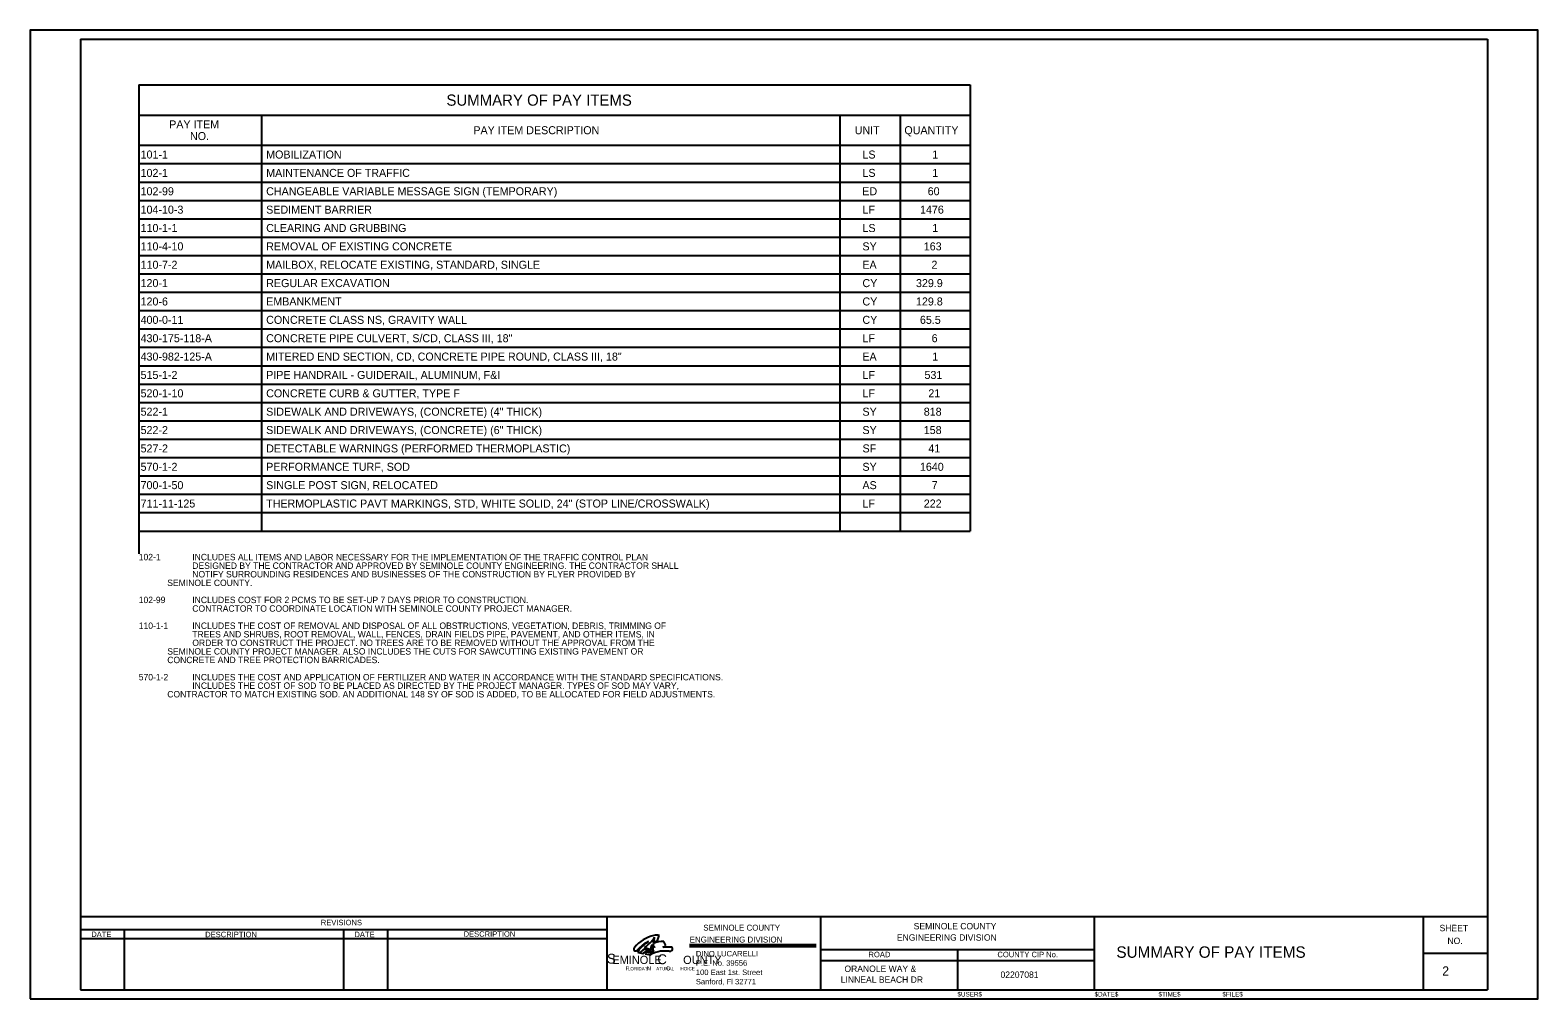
# Model space of a CAD drawing. Extents: x -792.8 to -776.3, y -2147.8 to -2137.2.
import ezdxf

# ---------------------------------------------------------------- set-up
doc = ezdxf.new("R2010")
doc.units = 0
for name, color, linetype in [('AdhocPoint_dp', 7, 'Continuous'), ('Default', 7, 'Continuous'), ('Logo_dp', 7, 'Continuous'), ('NonPlottingEle_dp', 7, 'Continuous'), ('PlotBorder_dp', 7, 'Continuous'), ('ScratchEle_dp', 7, 'Continuous'), ('SheetBorder_dp', 7, 'Continuous'), ('SheetLines_dp', 7, 'Continuous'), ('SumBoxBorder_dp', 7, 'Continuous'), ('SumBoxLines_dp', 7, 'Continuous'), ('SumBoxLinesMin_dp', 7, 'Continuous'), ('TextLabel', 7, 'Continuous'), ('TextMinor', 7, 'Continuous'), ('TextMisc', 7, 'Continuous'), ('TextShtNo', 7, 'Continuous')]:
    doc.layers.add(name, color=color, linetype=linetype)

msp = doc.modelspace()

# ---------------------------------------------------------------- linework, layer by layer
at = {"layer": 'AdhocPoint_dp'}
msp.add_line((-792.826, -2147.841), (-792.826, -2147.841), dxfattribs=at)
at = {"layer": 'Logo_dp'}
for p, q in [((-786.082, -2147.321), (-786.082, -2147.306)), ((-786.065, -2147.31), (-786.051, -2147.301)), ((-785.965, -2147.213), (-785.94, -2147.149)), ((-785.812, -2147.276), (-785.901, -2147.274)), ((-785.868, -2147.258), (-785.892, -2147.212)), ((-786.153, -2147.339), (-786.119, -2147.346)), ((-786.119, -2147.346), (-786.082, -2147.321)), ((-786.096, -2147.35), (-786.036, -2147.359)), ((-786.001, -2147.313), (-786.014, -2147.334))]:
    msp.add_line(p, q, dxfattribs=at)
for points in [[(-786.147, -2147.288), (-786.147, -2147.288)], [(-785.999, -2147.148), (-785.999, -2147.148)]]:
    msp.add_lwpolyline(points, dxfattribs=at)
for centre, radius, start, end in [((-785.971, -2147.269), 0.124, 75.3253, 102.9903), ((-786.189, -2147.297), 0.0305, 139.6059, 196.4516), ((-786.204, -2147.302), 0.015, 196.4516, 259.2243), ((-785.91, -2147.535), 0.397, 102.9903, 139.6059), ((-786.201, -2147.289), 0.0281, 259.2243, 316.3038), ((-785.905, -2147.544), 0.363, 114.9659, 139.5324), ((-786.063, -2147.368), 0.116, 136.5671, 163.5792), ((-785.974, -2147.497), 0.238, 117.2749, 138.5612), ((-785.974, -2147.497), 0.238, 117.2749, 138.5612), ((-785.805, -2147.612), 0.471, 122.4911, 136.5671), ((-786.397, -2146.85), 0.52, 304.6341, 315.4846), ((-786.128, -2147.373), 0.0982, 63.4009, 74.6531), ((-786.097, -2147.309), 0.0152, 9.3089, 39.4038), ((-786.092, -2147.327), 0.0288, 52.8844, 76.2699), ((-786.235, -2147.627), 0.374, 60.5981, 66.1485), ((-786.045, -2147.266), 0.0482, 231.8585, 245.4301), ((-785.687, -2147.855), 0.656, 120.5054, 124.3665), ((-785.868, -2147.333), 0.173, 149.8559, 166.6084), ((-785.883, -2147.578), 0.324, 115.0847, 118.1751), ((-786.152, -2147.091), 0.176, 315.4846, 334.5843), ((-785.917, -2147.273), 0.104, 164.7271, 186.2913), ((-785.982, -2147.285), 0.0385, 187.6078, 223.6575), ((-785.687, -2147.855), 0.656, 117.0216, 119.5789), ((-785.696, -2147.3), 0.315, 177.2074, 179.7242), ((-785.968, -2147.3), 0.0427, 177.7479, 195.3391), ((-785.696, -2147.3), 0.315, 168.5397, 176.4368), ((-785.883, -2147.578), 0.324, 108.2919, 113.1245), ((-785.897, -2147.455), 0.243, 88.8097, 116.3253), ((-786.217, -2147.161), 0.224, 343.2724, 358.4983), ((-785.925, -2147.392), 0.184, 102.6743, 114.927), ((-785.936, -2147.158), 0.122, 286.9862, 304.2368), ((-785.811, -2147.292), 0.0161, 0.9885, 92.5741), ((-785.822, -2147.294), 0.0268, 319.3898, 5.6197), ((-786.252, -2147.801), 0.472, 77.906, 80.5112), ((-785.823, -2147.569), 0.35, 136.6419, 141.2542), ((-786.031, -2147.132), 0.202, 256.604, 274.8219), ((-786.029, -2147.26), 0.0603, 242.5498, 297.6527), ((-785.854, -2147.706), 0.392, 100.5294, 117.6775), ((-785.878, -2147.844), 0.526, 84.8254, 95.1746), ((-785.826, -2147.282), 0.0383, 262.9671, 309.9257)]:
    msp.add_arc(centre, radius, start, end, dxfattribs=at)
at = {"layer": 'NonPlottingEle_dp'}
msp.add_line((-791.637, -2142.722), (-791.637, -2142.972), dxfattribs=at)
at = {"layer": 'PlotBorder_dp'}
msp.add_lwpolyline([(-792.826, -2147.841), (-776.326, -2147.841), (-776.326, -2137.241), (-792.826, -2137.241)], close=True, dxfattribs=at)
at = {"layer": 'SheetBorder_dp'}
for p, q in [((-792.276, -2137.341), (-792.276, -2147.741)), ((-792.276, -2137.341), (-776.876, -2137.341)), ((-776.876, -2137.341), (-776.876, -2147.741)), ((-792.276, -2146.941), (-776.876, -2146.941)), ((-792.276, -2147.741), (-776.876, -2147.741))]:
    msp.add_line(p, q, dxfattribs=at)
at = {"layer": 'SheetLines_dp'}
for p, q in [((-786.516, -2146.941), (-786.516, -2147.741)), ((-784.176, -2146.941), (-784.176, -2147.741)), ((-781.176, -2147.741), (-781.176, -2146.941)), ((-777.576, -2147.741), (-777.576, -2146.941)), ((-792.276, -2147.081), (-786.516, -2147.081)), ((-791.796, -2147.081), (-791.796, -2147.741)), ((-789.396, -2147.081), (-789.396, -2147.741)), ((-788.916, -2147.081), (-788.916, -2147.741)), ((-792.276, -2147.181), (-786.516, -2147.181)), ((-784.176, -2147.301), (-781.176, -2147.301)), ((-782.676, -2147.301), (-782.676, -2147.741)), ((-784.176, -2147.421), (-781.176, -2147.421)), ((-777.576, -2147.341), (-776.876, -2147.341))]:
    msp.add_line(p, q, dxfattribs=at)
at = {"layer": 'SumBoxBorder_dp'}
for p, q in [((-791.637, -2137.841), (-782.54, -2137.841)), ((-791.637, -2137.841), (-791.637, -2142.722)), ((-782.54, -2137.841), (-782.54, -2142.722)), ((-791.637, -2138.171), (-782.54, -2138.171)), ((-791.637, -2142.722), (-782.54, -2142.722))]:
    msp.add_line(p, q, dxfattribs=at)
at = {"layer": 'SumBoxLines_dp'}
for p, q in [((-790.295, -2138.171), (-790.295, -2142.722)), ((-790.295, -2138.171), (-790.295, -2142.722)), ((-783.965, -2138.171), (-783.965, -2142.722)), ((-783.965, -2138.171), (-783.965, -2142.722)), ((-783.305, -2138.171), (-783.305, -2142.722)), ((-783.305, -2138.171), (-783.305, -2142.722)), ((-791.637, -2138.501), (-782.54, -2138.501))]:
    msp.add_line(p, q, dxfattribs=at)
at = {"layer": 'SumBoxLinesMin_dp'}
for p, q in [((-791.637, -2138.501), (-782.54, -2138.501)), ((-791.637, -2138.702), (-782.54, -2138.702)), ((-791.637, -2138.702), (-782.54, -2138.702)), ((-791.637, -2138.903), (-782.54, -2138.903)), ((-791.637, -2138.903), (-782.54, -2138.903)), ((-791.637, -2139.104), (-782.54, -2139.104)), ((-791.637, -2139.104), (-782.54, -2139.104)), ((-791.637, -2139.305), (-782.54, -2139.305)), ((-791.637, -2139.305), (-782.54, -2139.305)), ((-791.637, -2139.506), (-782.54, -2139.506)), ((-791.637, -2139.506), (-782.54, -2139.506)), ((-791.637, -2139.707), (-782.54, -2139.707)), ((-791.637, -2139.707), (-782.54, -2139.707)), ((-791.637, -2139.908), (-782.54, -2139.908)), ((-791.637, -2139.908), (-782.54, -2139.908)), ((-791.637, -2140.109), (-782.54, -2140.109)), ((-791.637, -2140.109), (-782.54, -2140.109)), ((-791.637, -2140.31), (-782.54, -2140.31)), ((-791.637, -2140.31), (-782.54, -2140.31)), ((-791.637, -2140.511), (-782.54, -2140.511)), ((-791.637, -2140.511), (-782.54, -2140.511)), ((-791.637, -2140.712), (-782.54, -2140.712)), ((-791.637, -2140.712), (-782.54, -2140.712)), ((-791.637, -2140.913), (-782.54, -2140.913)), ((-791.637, -2140.913), (-782.54, -2140.913)), ((-791.637, -2141.114), (-782.54, -2141.114)), ((-791.637, -2141.114), (-782.54, -2141.114)), ((-791.637, -2141.315), (-782.54, -2141.315)), ((-791.637, -2141.315), (-782.54, -2141.315)), ((-791.637, -2141.516), (-782.54, -2141.516)), ((-791.637, -2141.516), (-782.54, -2141.516)), ((-791.637, -2141.717), (-782.54, -2141.717)), ((-791.637, -2141.717), (-782.54, -2141.717)), ((-791.637, -2141.918), (-782.54, -2141.918)), ((-791.637, -2141.918), (-782.54, -2141.918)), ((-791.637, -2142.119), (-782.54, -2142.119)), ((-791.637, -2142.119), (-782.54, -2142.119)), ((-791.637, -2142.32), (-782.54, -2142.32)), ((-791.637, -2142.32), (-782.54, -2142.32)), ((-791.637, -2142.521), (-782.54, -2142.521)), ((-791.637, -2142.521), (-782.54, -2142.521))]:
    msp.add_line(p, q, dxfattribs=at)
at = {"layer": 'TextMisc'}
for p, q in [((-785.611, -2147.269), (-784.225, -2147.269)), ((-785.609, -2147.247), (-784.223, -2147.247))]:
    msp.add_line(p, q, dxfattribs=at)

# ---------------------------------------------------------------- texts
at = {"layer": 'Default'}
for s, p in [('102-1', (-791.637, -2143.042)), (' INCLUDES ALL ITEMS AND LABOR NECESSARY FOR THE IMPLEMENTATION OF THE TRAFFIC CONTROL PLAN', (-791.077, -2143.042)), (' DESIGNED BY THE CONTRACTOR AND APPROVED BY SEMINOLE COUNTY ENGINEERING. THE CONTRACTOR SHALL', (-791.077, -2143.136)), (' NOTIFY SURROUNDING RESIDENCES AND BUSINESSES OF THE CONSTRUCTION BY FLYER PROVIDED BY ', (-791.077, -2143.23)), ('            SEMINOLE COUNTY.', (-791.637, -2143.324)), ('102-99', (-791.637, -2143.511)), (' INCLUDES COST FOR 2 PCMS TO BE SET-UP 7 DAYS PRIOR TO CONSTRUCTION.  ', (-791.077, -2143.511)), (' CONTRACTOR TO COORDINATE LOCATION WITH SEMINOLE COUNTY PROJECT MANAGER.', (-791.077, -2143.605)), ('110-1-1', (-791.637, -2143.793)), (' TREES AND SHRUBS, ROOT REMOVAL, WALL, FENCES, DRAIN FIELDS PIPE, PAVEMENT, AND OTHER ITEMS, IN ', (-791.077, -2143.887)), (' INCLUDES THE COST OF REMOVAL AND DISPOSAL OF ALL OBSTRUCTIONS, VEGETATION, DEBRIS, TRIMMING OF ', (-791.077, -2143.793)), ('            SEMINOLE COUNTY PROJECT MANAGER. ALSO INCLUDES THE CUTS FOR SAWCUTTING EXISTING PAVEMENT OR ', (-791.637, -2144.074)), (' ORDER TO CONSTRUCT THE PROJECT. NO TREES ARE TO BE REMOVED WITHOUT THE APPROVAL FROM THE ', (-791.077, -2143.98)), ('            CONCRETE AND TREE PROTECTION BARRICADES.', (-791.637, -2144.168)), ('570-1-2 ', (-791.637, -2144.356)), (' INCLUDES THE COST AND APPLICATION OF FERTILIZER AND WATER IN ACCORDANCE WITH THE STANDARD SPECIFICATIONS. ', (-791.077, -2144.356)), ('            CONTRACTOR TO MATCH EXISTING SOD. AN ADDITIONAL 148 SY OF SOD IS ADDED, TO BE ALLOCATED FOR FIELD ADJUSTMENTS.', (-791.637, -2144.543)), (' INCLUDES THE COST OF SOD TO BE PLACED AS DIRECTED BY THE PROJECT MANAGER. TYPES OF SOD MAY VARY,', (-791.077, -2144.449))]:
    msp.add_text(s, height=0.07, dxfattribs=at).set_placement(p)
at = {"layer": 'Logo_dp'}
for s, height, p in [('S', 0.108, (-786.513, -2147.456)), ('EMINOLE       OUNTY', 0.09, (-786.455, -2147.46)), ('C', 0.108, (-785.961, -2147.462)), ('F', 0.045, (-786.309, -2147.531)), ("LORIDA'S      ATURAL     HOICE", 0.036, (-786.285, -2147.529)), ('N', 0.045, (-786.075, -2147.531)), ('C', 0.045, (-785.866, -2147.531))]:
    msp.add_text(s, height=height, dxfattribs=at).set_placement(p)
at = {"layer": 'ScratchEle_dp'}
for s, p in [('Angle:  90.0153', (-792.276, -2146.943)), ('Align: CH269', (-792.276, -2146.947)), ('Sheet: 1', (-792.276, -2146.939))]:
    msp.add_text(s, height=0.00295, dxfattribs=at).set_placement(p)
at = {"layer": 'TextLabel'}
for s, height, p in [('SUMMARY OF PAY ITEMS', 0.1225, (-788.27, -2138.068)), ('PAY ITEM', 0.0875, (-791.304, -2138.316)), ('NO.', 0.0875, (-791.076, -2138.444)), ('PAY ITEM DESCRIPTION', 0.0875, (-787.975, -2138.38)), ('UNIT', 0.0875, (-783.802, -2138.38)), ('QUANTITY', 0.0875, (-783.258, -2138.38)), ('101-1', 0.0875, (-791.617, -2138.646)), (' MOBILIZATION', 0.0875, (-790.275, -2138.646)), ('LS', 0.0875, (-783.717, -2138.646)), ('1', 0.0875, (-782.953, -2138.646)), ('102-1', 0.0875, (-791.617, -2138.847)), (' MAINTENANCE OF TRAFFIC', 0.0875, (-790.275, -2138.847)), ('LS', 0.0875, (-783.717, -2138.847)), ('1', 0.0875, (-782.953, -2138.847)), ('102-99', 0.0875, (-791.617, -2139.048)), (' CHANGEABLE VARIABLE MESSAGE SIGN (TEMPORARY)', 0.0875, (-790.275, -2139.048)), ('ED', 0.0875, (-783.719, -2139.048)), ('60', 0.0875, (-783.003, -2139.048)), ('104-10-3', 0.0875, (-791.617, -2139.249)), (' SEDIMENT BARRIER', 0.0875, (-790.275, -2139.249)), ('LF', 0.0875, (-783.716, -2139.249)), ('1476', 0.0875, (-783.087, -2139.249)), ('110-1-1', 0.0875, (-791.617, -2139.45)), (' CLEARING AND GRUBBING', 0.0875, (-790.275, -2139.45)), ('LS', 0.0875, (-783.717, -2139.45)), ('1', 0.0875, (-782.953, -2139.45)), ('110-4-10', 0.0875, (-791.617, -2139.651)), (' REMOVAL OF EXISTING CONCRETE', 0.0875, (-790.275, -2139.651)), ('SY', 0.0875, (-783.717, -2139.651)), ('163', 0.0875, (-783.046, -2139.651)), ('110-7-2', 0.0875, (-791.617, -2139.852)), (' MAILBOX, RELOCATE EXISTING, STANDARD, SINGLE', 0.0875, (-790.275, -2139.852)), ('EA', 0.0875, (-783.718, -2139.852)), ('2', 0.0875, (-782.962, -2139.852)), ('120-1', 0.0875, (-791.617, -2140.053)), (' REGULAR EXCAVATION', 0.0875, (-790.275, -2140.053)), ('CY', 0.0875, (-783.717, -2140.053)), ('329.9', 0.0875, (-783.131, -2140.053)), ('120-6', 0.0875, (-791.617, -2140.254)), (' EMBANKMENT', 0.0875, (-790.275, -2140.254)), ('CY', 0.0875, (-783.717, -2140.254)), ('129.8', 0.0875, (-783.131, -2140.254)), ('400-0-11', 0.0875, (-791.617, -2140.455)), (' CONCRETE CLASS NS, GRAVITY WALL', 0.0875, (-790.275, -2140.455)), ('CY', 0.0875, (-783.717, -2140.455)), ('65.5', 0.0875, (-783.088, -2140.455)), ('430-175-118-A', 0.0875, (-791.617, -2140.656)), (' CONCRETE PIPE CULVERT, S/CD, CLASS III, 18"', 0.0875, (-790.275, -2140.656)), ('LF', 0.0875, (-783.716, -2140.656)), ('6', 0.0875, (-782.96, -2140.656)), ('430-982-125-A', 0.0875, (-791.617, -2140.857)), (' MITERED END SECTION, CD, CONCRETE PIPE ROUND, CLASS III, 18"', 0.0875, (-790.275, -2140.857)), ('EA', 0.0875, (-783.718, -2140.857)), ('1', 0.0875, (-782.953, -2140.857)), ('515-1-2', 0.0875, (-791.617, -2141.058)), (' PIPE HANDRAIL - GUIDERAIL, ALUMINUM, F&I', 0.0875, (-790.275, -2141.058)), ('LF', 0.0875, (-783.716, -2141.058)), ('531', 0.0875, (-783.038, -2141.058)), ('520-1-10', 0.0875, (-791.617, -2141.259)), (' CONCRETE CURB & GUTTER, TYPE F', 0.0875, (-790.275, -2141.259)), ('LF', 0.0875, (-783.716, -2141.259)), ('21', 0.0875, (-782.996, -2141.259)), (' SIDEWALK AND DRIVEWAYS, (CONCRETE) (4" THICK)', 0.0875, (-790.275, -2141.46)), ('522-1', 0.0875, (-791.617, -2141.46)), ('SY', 0.0875, (-783.717, -2141.46)), ('818', 0.0875, (-783.046, -2141.46)), ('522-2', 0.0875, (-791.617, -2141.661)), (' SIDEWALK AND DRIVEWAYS, (CONCRETE) (6" THICK)', 0.0875, (-790.275, -2141.661)), ('SY', 0.0875, (-783.717, -2141.661)), ('158', 0.0875, (-783.046, -2141.661)), ('527-2', 0.0875, (-791.617, -2141.862)), (' DETECTABLE WARNINGS (PERFORMED THERMOPLASTIC)', 0.0875, (-790.275, -2141.862)), ('SF', 0.0875, (-783.716, -2141.862)), ('41', 0.0875, (-782.996, -2141.862)), ('570-1-2', 0.0875, (-791.617, -2142.063)), (' PERFORMANCE TURF, SOD', 0.0875, (-790.275, -2142.063)), ('SY', 0.0875, (-783.717, -2142.063)), ('1640', 0.0875, (-783.088, -2142.063)), ('700-1-50', 0.0875, (-791.617, -2142.264)), (' SINGLE POST SIGN, RELOCATED', 0.0875, (-790.275, -2142.264)), ('AS', 0.0875, (-783.717, -2142.264)), ('7', 0.0875, (-782.959, -2142.264)), ('711-11-125', 0.0875, (-791.617, -2142.465)), (' THERMOPLASTIC PAVT MARKINGS, STD, WHITE SOLID, 24" (STOP LINE/CROSSWALK)', 0.0875, (-790.275, -2142.465)), ('LF', 0.0875, (-783.716, -2142.465)), ('222', 0.0875, (-783.046, -2142.465))]:
    msp.add_text(s, height=height, dxfattribs=at).set_placement(p)
at = {"layer": 'TextMinor'}
for s, p in [('$USER$', (-782.677, -2147.816)), ('$DATE$', (-781.177, -2147.816)), ('$TIME$', (-780.477, -2147.816)), ('$FILE$', (-779.777, -2147.816))]:
    msp.add_text(s, height=0.05, rotation=360, dxfattribs=at).set_placement(p)
at = {"layer": 'TextMisc'}
for s, height, rotation, p in [('REVISIONS', 0.06, 360, (-789.645, -2147.036)), ('DATE', 0.06, 359.8693, (-792.157, -2147.165)), ('DESCRIPTION', 0.06, 0.0498, (-790.91, -2147.167)), ('DATE', 0.06, 359.8693, (-789.277, -2147.166)), ('DESCRIPTION', 0.06, 0.0498, (-788.082, -2147.162)), ('ENGINEERING DIVISION', 0.07, 360, (-783.34, -2147.205)), ('SEMINOLE COUNTY', 0.07, 360, (-783.156, -2147.081)), ('SHEET', 0.07, 359.8607, (-777.401, -2147.101)), ('NO.', 0.07, 359.8607, (-777.315, -2147.241)), ('ROAD', 0.06, 360, (-783.651, -2147.386)), ('COUNTY CIP No.', 0.06, 360, (-782.24, -2147.386)), (' LINNEAL BEACH DR', 0.07, 360, (-783.98, -2147.666)), ('ORANOLE WAY & ', 0.07, 360, (-783.914, -2147.547)), ('   02207081   ', 0.07, 360, (-782.284, -2147.612))]:
    msp.add_text(s, height=height, rotation=rotation, dxfattribs=at).set_placement(p)
for s, height, p in [('SEMINOLE COUNTY', 0.065, (-785.459, -2147.095)), ('ENGINEERING DIVISION', 0.065, (-785.608, -2147.225)), ('     SUMMARY OF PAY ITEMS      ', 0.125, (-781.17, -2147.392)), ('DINO LUCARELLI', 0.06, (-785.54, -2147.377)), ('P.E. No. 39556', 0.06, (-785.54, -2147.479)), ('Sanford, Fl 32771', 0.06, (-785.54, -2147.683)), ('100 East 1st. Street', 0.06, (-785.54, -2147.581))]:
    msp.add_text(s, height=height, dxfattribs=at).set_placement(p)
at = {"layer": 'TextShtNo'}
msp.add_text('  2   ', height=0.1, dxfattribs=at).set_placement((-777.446, -2147.586))

doc.saveas('drawing.dxf')
